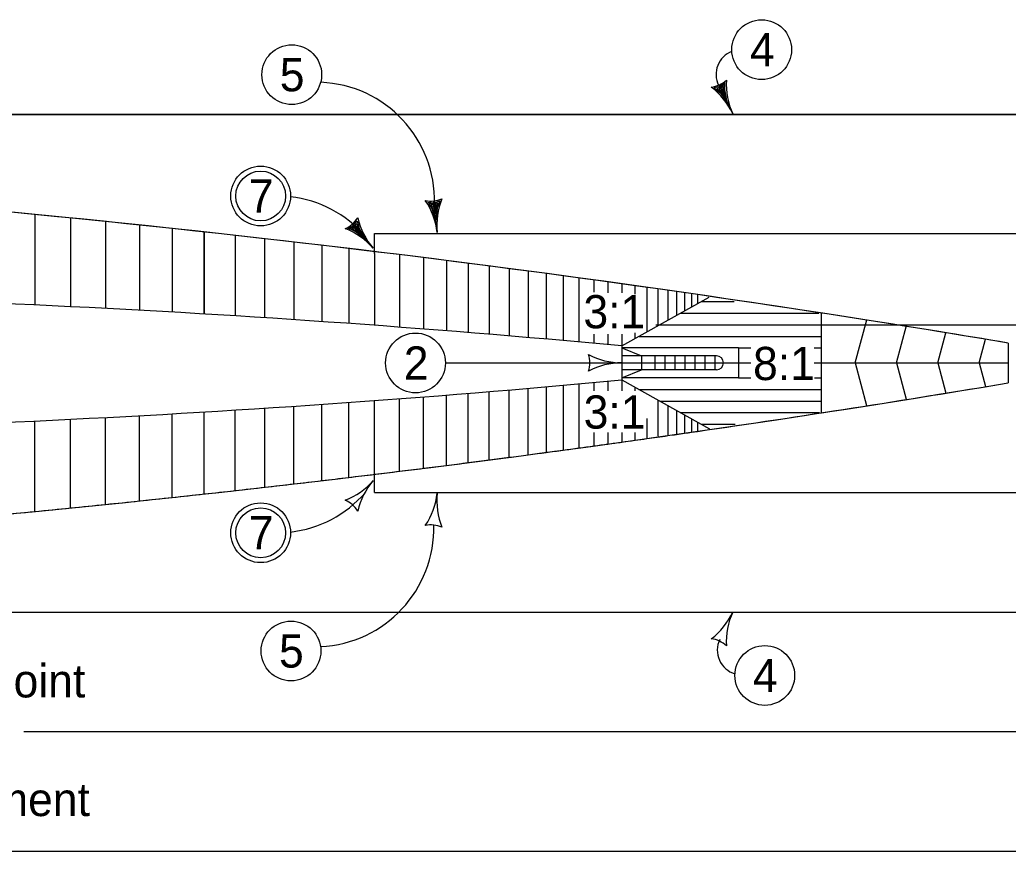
# Model space of a CAD drawing. Extents: x -2135039 to -2131695, y -2139150 to -2136566.
# Drawn here: x -2133841 to -2133246, y -2138502 to -2138002 of the extents above; entities that cross this region are included whole.
import ezdxf

# ---------------------------------------------------------------- set-up
doc = ezdxf.new("R2010")
doc.units = 0
for name, color, linetype in [('dsnStdDimension', 7, 'Continuous'), ('dsnStdLineDrawingWt4', 7, 'Continuous'), ('dsnStdShading', 7, 'Continuous'), ('Level 10', 7, 'Continuous'), ('Level 2', 7, 'Continuous'), ('Level 3', 7, 'Continuous'), ('Level 5', 7, 'Continuous'), ('Level 7', 7, 'Continuous')]:
    doc.layers.add(name, color=color, linetype=linetype)

msp = doc.modelspace()

# ---------------------------------------------------------------- linework, layer by layer
at = {"layer": 'dsnStdDimension'}
for p, q in [((-2133411.43, -2138058.5), (-2133419.43, -2138041.02)), ((-2133589.28, -2138130.01), (-2133591.41, -2138110.91)), ((-2133627.82, -2138139.45), (-2133640.43, -2138124.94)), ((-2133584.37, -2138208.43), (-2133478.24, -2138208.43))]:
    msp.add_line(p, q, dxfattribs=at)
for points in [[(-2133416.03, -2138039.9), (-2133418.98, -2138042.04), (-2133422.57, -2138042.86), (-2133418.9, -2138045.9), (-2133414.67, -2138051.47), (-2133416.16, -2138044.09), (-2133416.19, -2138040.63), (-2133418.71, -2138042.64), (-2133420.94, -2138043.33), (-2133418.53, -2138045.34), (-2133416.08, -2138048.38), (-2133416.69, -2138044.23), (-2133416.91, -2138042.02), (-2133419.54, -2138043.65), (-2133417.31, -2138045.7), (-2133417.59, -2138043.42), (-2133418.56, -2138043.83), (-2133417.83, -2138044.62)], [(-2133594.91, -2138111.69), (-2133591.27, -2138112.01), (-2133587.77, -2138110.87), (-2133589.35, -2138115.37), (-2133590.12, -2138122.32), (-2133592.64, -2138115.22), (-2133594.39, -2138112.24), (-2133591.2, -2138112.67), (-2133588.93, -2138112.11), (-2133589.96, -2138115.07), (-2133590.5, -2138118.94), (-2133592.11, -2138115.07), (-2133593.06, -2138113.06), (-2133589.97, -2138113.11), (-2133590.82, -2138116.02), (-2133591.75, -2138113.91), (-2133590.71, -2138113.77), (-2133590.93, -2138114.82)], [(-2133642.86, -2138127.57), (-2133639.68, -2138125.77), (-2133637.46, -2138122.84), (-2133636.2, -2138127.44), (-2133632.88, -2138133.6), (-2133638.99, -2138129.18), (-2133642.12, -2138127.73), (-2133639.25, -2138126.27), (-2133637.7, -2138124.52), (-2133636.87, -2138127.54), (-2133635.11, -2138131.03), (-2133638.64, -2138128.76), (-2133640.56, -2138127.65), (-2133637.99, -2138125.93), (-2133637.04, -2138128.81), (-2133639, -2138127.61), (-2133638.23, -2138126.89), (-2133637.81, -2138127.88)]]:
    msp.add_lwpolyline(points, dxfattribs=at)
for centre, radius, start, end in [((-2133406.49, -2138034.85), 15, 111.38245, 205.29266), ((-2133662.38, -2138110.89), 71.46, 358.52569, 87.65401), ((-2133426.27, -2138026.09), 16.42, 276.86459, 312.33129), ((-2133450.08, -2138076.19), 42.5, 24.59794, 52.67043), ((-2133372.79, -2138040.81), 42.5, 176.52545, 204.59794), ((-2133685.57, -2138177.98), 70, 40.99055, 83.44185), ((-2133593.23, -2138094.59), 16.42, 258.64458, 294.11128), ((-2133631.51, -2138134.73), 42.5, 6.37793, 34.45042), ((-2133547.04, -2138125.29), 42.5, 158.30544, 186.37793), ((-2133651.19, -2138112.55), 16.42, 293.25942, 328.72612), ((-2133595.74, -2138111.57), 42.5, 192.92028, 220.99277), ((-2133659.9, -2138167.32), 42.5, 40.99277, 69.06526), ((-2133513.87, -2138208.43), 16.42, 342.26665, 17.73335), ((-2133478.24, -2138165.93), 42.5, 241.92751, 270), ((-2133478.24, -2138250.93), 42.5, 90, 118.07249), ((-2133659.9, -2138251.4), 42.5, 290.93474, 319.00723), ((-2133595.74, -2138307.15), 42.5, 139.00723, 167.07972), ((-2133685.57, -2138240.75), 70, 276.55825, 319.00945), ((-2133651.19, -2138306.17), 16.42, 31.27388, 66.74058), ((-2133631.51, -2138282.26), 42.5, 325.54958, 353.62207), ((-2133547.04, -2138291.71), 42.5, 173.62207, 201.69456), ((-2133662.83, -2138307.91), 71.46, 272.66511, 1.47431), ((-2133593.23, -2138322.4), 16.42, 65.88872, 101.35542), ((-2133450.08, -2138340.81), 42.5, 307.32957, 335.40206), ((-2133372.79, -2138376.19), 42.5, 155.40206, 183.47455), ((-2133426.27, -2138390.9), 16.42, 47.66871, 83.13541), ((-2133405.7, -2138381.36), 15, 154.70734, 252.90173)]:
    msp.add_arc(centre, radius, start, end, dxfattribs=at)
at = {"layer": 'dsnStdLineDrawingWt4'}
for p, q in [((-2134688.01, -2138058.83), (-2133150.73, -2138058.83)), ((-2133831.57, -2138119.08), (-2133831.57, -2138173.56)), ((-2133809.97, -2138121.21), (-2133809.97, -2138174.6)), ((-2133788.98, -2138123.33), (-2133788.98, -2138175.67)), ((-2133768.58, -2138125.44), (-2133768.58, -2138176.76)), ((-2133748.78, -2138127.54), (-2133748.78, -2138177.87)), ((-2133729.58, -2138129.61), (-2133729.58, -2138179)), ((-2133729.58, -2138179), (-2133729.58, -2138129.61)), ((-2133710.98, -2138131.67), (-2133710.98, -2138180.14)), ((-2133626.99, -2138142.5), (-2133626.99, -2138130.5)), ((-2133626.99, -2138130.5), (-2132916.93, -2138130.5)), ((-2133693.19, -2138133.67), (-2133693.19, -2138181.27)), ((-2133675.58, -2138135.69), (-2133675.58, -2138182.43)), ((-2133658.78, -2138137.65), (-2133658.78, -2138183.58)), ((-2133642.58, -2138139.57), (-2133642.58, -2138184.72)), ((-2133626.98, -2138142.5), (-2133626.98, -2138185.85)), ((-2133611.98, -2138143.29), (-2133611.98, -2138186.97)), ((-2133597.58, -2138145.08), (-2133597.58, -2138188.07)), ((-2133583.78, -2138146.82), (-2133583.78, -2138189.15)), ((-2133570.58, -2138148.5), (-2133570.58, -2138190.21)), ((-2133557.98, -2138150.12), (-2133557.98, -2138191.24)), ((-2133545.98, -2138151.69), (-2133545.98, -2138192.24)), ((-2133534.58, -2138153.19), (-2133534.58, -2138193.21)), ((-2133523.78, -2138154.63), (-2133523.78, -2138194.14)), ((-2133513.58, -2138156), (-2133513.58, -2138195.04)), ((-2133503.98, -2138157.3), (-2133503.98, -2138195.89)), ((-2133494.98, -2138158.53), (-2133494.98, -2138165.9)), ((-2133486.58, -2138159.69), (-2133486.58, -2138166.25)), ((-2133478.18, -2138160.85), (-2133478.18, -2138166.25)), ((-2133470.38, -2138161.94), (-2133470.38, -2138167.05)), ((-2133463.18, -2138162.96), (-2133463.18, -2138189.9)), ((-2133456.58, -2138163.89), (-2133456.58, -2138186.2)), ((-2133450.58, -2138164.74), (-2133450.58, -2138182.85)), ((-2133445.18, -2138165.52), (-2133445.18, -2138179.83)), ((-2133440.38, -2138166.2), (-2133440.38, -2138177.14)), ((-2133436.18, -2138166.81), (-2133436.18, -2138174.79)), ((-2133432.58, -2138167.33), (-2133432.58, -2138172.78)), ((-2133478.13, -2138198.26), (-2133425.54, -2138168.84)), ((-2133430.24, -2138171.55), (-2133410.47, -2138171.55)), ((-2133442.86, -2138178.53), (-2133359.66, -2138178.53)), ((-2133358.24, -2138178.73), (-2133358.24, -2138238.26)), ((-2133455.33, -2138185.51), (-2133358.24, -2138185.51)), ((-2133337.7, -2138208.46), (-2133330.77, -2138182.6)), ((-2133494.98, -2138191.1), (-2133494.98, -2138196.71)), ((-2133486.58, -2138191.25), (-2133486.58, -2138197.48)), ((-2133478.18, -2138191.25), (-2133478.18, -2138225.31)), ((-2133470.38, -2138190.45), (-2133470.38, -2138193.92)), ((-2133312.84, -2138208.5), (-2133306.82, -2138186.03)), ((-2133287.99, -2138208.5), (-2133283.15, -2138190.4)), ((-2133486.58, -2138192), (-2133486.58, -2138193.21)), ((-2133467.81, -2138192.49), (-2133358.24, -2138192.49)), ((-2133263.15, -2138208.5), (-2133259.33, -2138194.25)), ((-2133245.58, -2138196.5), (-2133245.58, -2138220.5)), ((-2133478.24, -2138198.26), (-2133478.24, -2138218.73)), ((-2133408.04, -2138199.46), (-2133478.24, -2138199.46)), ((-2133478.24, -2138199.46), (-2133466.24, -2138204.26)), ((-2133408.04, -2138199.46), (-2133408.04, -2138217.46)), ((-2133408.04, -2138199.46), (-2133400.53, -2138199.46)), ((-2133362.36, -2138199.46), (-2133358.24, -2138199.46)), ((-2133466.24, -2138204.26), (-2133478.24, -2138204.26)), ((-2133478.24, -2138208.5), (-2133400.53, -2138208.5)), ((-2133421.24, -2138204.26), (-2133466.24, -2138204.26)), ((-2133466.24, -2138204.26), (-2133466.24, -2138212.66)), ((-2133458.24, -2138204.26), (-2133458.24, -2138212.66)), ((-2133452.24, -2138204.26), (-2133452.24, -2138212.66)), ((-2133446.24, -2138204.26), (-2133446.24, -2138212.66)), ((-2133440.24, -2138204.26), (-2133440.24, -2138212.66)), ((-2133434.24, -2138204.26), (-2133434.24, -2138212.66)), ((-2133428.24, -2138204.26), (-2133428.24, -2138212.66)), ((-2133422.24, -2138204.26), (-2133422.24, -2138212.66)), ((-2133362.36, -2138208.5), (-2133245.58, -2138208.5)), ((-2133337.7, -2138208.46), (-2133330.83, -2138234.08)), ((-2133312.84, -2138208.5), (-2133306.98, -2138230.37)), ((-2133288, -2138208.5), (-2133283.15, -2138226.59)), ((-2133263.15, -2138208.5), (-2133259.33, -2138222.75)), ((-2133478.24, -2138217.46), (-2133466.24, -2138212.66)), ((-2133466.24, -2138212.66), (-2133478.24, -2138212.66)), ((-2133421.24, -2138212.66), (-2133466.24, -2138212.66)), ((-2133503.98, -2138221.1), (-2133503.98, -2138259.7)), ((-2133494.98, -2138220.29), (-2133494.98, -2138225.31)), ((-2133486.58, -2138219.52), (-2133486.58, -2138225.31)), ((-2133408.04, -2138217.46), (-2133478.24, -2138217.46)), ((-2133478.12, -2138218.73), (-2133425.45, -2138248.14)), ((-2133408.04, -2138217.46), (-2133400.53, -2138217.46)), ((-2133362.2, -2138217.46), (-2133358.24, -2138217.46)), ((-2133570.58, -2138268.5), (-2133570.58, -2138226.79)), ((-2133557.98, -2138266.88), (-2133557.98, -2138225.76)), ((-2133545.98, -2138265.31), (-2133545.98, -2138224.75)), ((-2133534.58, -2138263.81), (-2133534.58, -2138223.79)), ((-2133523.78, -2138222.85), (-2133523.78, -2138262.37)), ((-2133513.58, -2138221.96), (-2133513.58, -2138261)), ((-2133470.38, -2138223.06), (-2133470.38, -2138225.31)), ((-2133467.89, -2138224.44), (-2133358.24, -2138224.44)), ((-2133642.58, -2138277.42), (-2133642.58, -2138232.28)), ((-2133626.98, -2138275.54), (-2133626.98, -2138231.14)), ((-2133611.98, -2138273.71), (-2133611.98, -2138230.03)), ((-2133597.58, -2138271.92), (-2133597.58, -2138228.93)), ((-2133583.78, -2138270.18), (-2133583.78, -2138227.84)), ((-2133456.58, -2138230.76), (-2133456.58, -2138252.52)), ((-2133455.4, -2138231.42), (-2133358.24, -2138231.42)), ((-2133748.78, -2138289.46), (-2133748.78, -2138239.12)), ((-2133729.58, -2138287.39), (-2133729.58, -2138237.99)), ((-2133710.98, -2138285.33), (-2133710.98, -2138236.86)), ((-2133692.98, -2138283.3), (-2133692.98, -2138235.71)), ((-2133675.58, -2138281.31), (-2133675.58, -2138234.56)), ((-2133658.78, -2138279.35), (-2133658.78, -2138233.42)), ((-2133450.58, -2138234.11), (-2133450.58, -2138252.25)), ((-2133445.18, -2138237.12), (-2133445.18, -2138251.48)), ((-2133442.9, -2138238.4), (-2133359.2, -2138238.4)), ((-2133831.57, -2138297.92), (-2133831.57, -2138243.43)), ((-2133809.97, -2138295.79), (-2133809.97, -2138242.39)), ((-2133788.98, -2138293.67), (-2133788.98, -2138241.33)), ((-2133768.58, -2138291.56), (-2133768.58, -2138240.23)), ((-2133463.18, -2138242.01), (-2133463.18, -2138254.04)), ((-2133440.38, -2138239.8), (-2133440.38, -2138250.79)), ((-2133436.18, -2138242.15), (-2133436.18, -2138250.19)), ((-2133432.58, -2138244.16), (-2133432.58, -2138249.67)), ((-2133494.98, -2138250.31), (-2133494.98, -2138258.47)), ((-2133486.58, -2138250.29), (-2133486.58, -2138257.31)), ((-2133478.18, -2138250.31), (-2133478.18, -2138256.14)), ((-2133470.38, -2138250.31), (-2133470.38, -2138255.05)), ((-2133430.24, -2138245.37), (-2133409.99, -2138245.37)), ((-2133626.99, -2138286.5), (-2133626.99, -2138274.5)), ((-2133626.99, -2138286.5), (-2132913.93, -2138286.5)), ((-2134688.98, -2138358.5), (-2133150.73, -2138358.5)), ((-2134750.5, -2138502.5), (-2132911.43, -2138502.5))]:
    msp.add_line(p, q, dxfattribs=at)
for centre, radius, start, end in [((-2134663.92, -2146675.65), 8596.96, 80.503855, 86.524933), ((-2134186.74, -2145798.55), 7633.25, 84.674283, 90), ((-2134186.74, -2130618.44), 7633.25, 270, 275.326608), ((-2134663.85, -2129742.69), 8595.62, 273.476084, 279.497162)]:
    msp.add_arc(centre, radius, start, end, dxfattribs=at)
at = {"layer": 'dsnStdShading'}
for p, q in [((-2133150.73, -2138058.83), (-2134688.01, -2138058.83)), ((-2133693.19, -2138133.67), (-2133693.19, -2138133.67)), ((-2133330.79, -2138182.68), (-2133330.77, -2138182.6)), ((-2133245.58, -2138196.5), (-2133245.58, -2138208.5)), ((-2133245.58, -2138208.5), (-2133245.58, -2138220.5)), ((-2133440.38, -2138250.79), (-2133440.38, -2138250.79)), ((-2133436.18, -2138250.19), (-2133436.18, -2138250.19)), ((-2133432.58, -2138249.67), (-2133432.58, -2138249.67)), ((-2133478.18, -2138256.14), (-2133478.18, -2138256.14)), ((-2133470.38, -2138255.05), (-2133470.38, -2138255.05)), ((-2133463.18, -2138254.04), (-2133463.18, -2138254.04)), ((-2133450.58, -2138252.25), (-2133450.58, -2138252.25)), ((-2133445.18, -2138251.48), (-2133445.18, -2138251.48)), ((-2133523.78, -2138262.37), (-2133523.78, -2138262.37)), ((-2133513.58, -2138261), (-2133513.58, -2138261)), ((-2133503.98, -2138259.7), (-2133503.98, -2138259.7)), ((-2133494.98, -2138258.47), (-2133494.98, -2138258.47)), ((-2133486.58, -2138257.31), (-2133486.58, -2138257.31)), ((-2133570.58, -2138268.5), (-2133570.58, -2138268.5)), ((-2133557.98, -2138266.88), (-2133557.98, -2138266.88)), ((-2133545.98, -2138265.31), (-2133545.98, -2138265.31)), ((-2133534.58, -2138263.81), (-2133534.58, -2138263.81)), ((-2133611.98, -2138273.71), (-2133611.98, -2138273.71)), ((-2133597.58, -2138271.92), (-2133597.58, -2138271.92)), ((-2133583.78, -2138270.18), (-2133583.78, -2138270.18)), ((-2133658.78, -2138279.35), (-2133658.78, -2138279.35)), ((-2133642.58, -2138277.42), (-2133642.58, -2138277.42)), ((-2133626.98, -2138275.54), (-2133626.98, -2138275.54)), ((-2133710.98, -2138285.33), (-2133710.98, -2138285.33)), ((-2133692.98, -2138283.3), (-2133692.98, -2138283.3)), ((-2133675.58, -2138281.31), (-2133675.58, -2138281.31)), ((-2133768.58, -2138291.56), (-2133768.58, -2138291.56)), ((-2133748.78, -2138289.46), (-2133748.78, -2138289.46)), ((-2133729.58, -2138287.39), (-2133729.58, -2138287.39)), ((-2133831.57, -2138297.92), (-2133831.57, -2138297.92)), ((-2133809.97, -2138295.79), (-2133809.97, -2138295.79)), ((-2133788.98, -2138293.67), (-2133788.98, -2138293.67)), ((-2134688.98, -2138358.5), (-2133150.73, -2138358.5))]:
    msp.add_line(p, q, dxfattribs=at)
for points in [[(-2133693.19, -2138133.67), (-2133693.19, -2138133.67)], [(-2133330.77, -2138182.6), (-2133330.78, -2138182.68)], [(-2133440.38, -2138250.79), (-2133440.38, -2138250.79)], [(-2133436.18, -2138250.19), (-2133436.18, -2138250.19)], [(-2133432.58, -2138249.67), (-2133432.58, -2138249.67)], [(-2133478.18, -2138256.14), (-2133478.18, -2138256.14)], [(-2133470.38, -2138255.05), (-2133470.38, -2138255.05)], [(-2133463.18, -2138254.04), (-2133463.18, -2138254.04)], [(-2133450.58, -2138252.25), (-2133450.58, -2138252.25)], [(-2133445.18, -2138251.48), (-2133445.18, -2138251.48)], [(-2133523.78, -2138262.37), (-2133523.78, -2138262.37)], [(-2133513.58, -2138261), (-2133513.58, -2138261)], [(-2133503.98, -2138259.7), (-2133503.98, -2138259.7)], [(-2133494.98, -2138258.47), (-2133494.98, -2138258.47)], [(-2133486.58, -2138257.31), (-2133486.58, -2138257.31)], [(-2133570.58, -2138268.5), (-2133570.58, -2138268.5)], [(-2133557.98, -2138266.88), (-2133557.98, -2138266.88)], [(-2133545.98, -2138265.31), (-2133545.98, -2138265.31)], [(-2133534.58, -2138263.81), (-2133534.58, -2138263.81)], [(-2133611.98, -2138273.71), (-2133611.98, -2138273.71)], [(-2133597.58, -2138271.92), (-2133597.58, -2138271.92)], [(-2133583.78, -2138270.18), (-2133583.78, -2138270.18)], [(-2133658.78, -2138279.35), (-2133658.78, -2138279.35)], [(-2133642.58, -2138277.42), (-2133642.58, -2138277.42)], [(-2133626.98, -2138275.54), (-2133626.98, -2138275.54)], [(-2133710.98, -2138285.33), (-2133710.98, -2138285.33)], [(-2133692.98, -2138283.3), (-2133692.98, -2138283.3)], [(-2133675.58, -2138281.31), (-2133675.58, -2138281.31)], [(-2133768.58, -2138291.56), (-2133768.58, -2138291.56)], [(-2133748.78, -2138289.46), (-2133748.78, -2138289.46)], [(-2133729.58, -2138287.39), (-2133729.58, -2138287.39)], [(-2133831.57, -2138297.92), (-2133831.57, -2138297.92)], [(-2133809.97, -2138295.79), (-2133809.97, -2138295.79)], [(-2133788.98, -2138293.67), (-2133788.98, -2138293.67)]]:
    msp.add_lwpolyline(points, dxfattribs=at)
for centre, radius, start, end in [((-2134663.92, -2146675.65), 8596.96, 83.516635, 86.489906), ((-2134663.92, -2146675.65), 8596.96, 81.079166, 83.516635), ((-2134663.92, -2146675.65), 8596.96, 80.503855, 81.079108), ((-2134663.85, -2129742.69), 8595.62, 278.235608, 279.497162), ((-2134663.85, -2129742.69), 8595.62, 278.150755, 278.183078), ((-2134663.85, -2129742.69), 8595.62, 278.183078, 278.211362), ((-2134663.85, -2129742.69), 8595.62, 278.211363, 278.235608), ((-2134663.85, -2129742.69), 8595.62, 277.872075, 277.928603), ((-2134663.85, -2129742.69), 8595.62, 277.928604, 277.981101), ((-2134663.85, -2129742.69), 8595.62, 277.981101, 278.029566), ((-2134663.85, -2129742.69), 8595.62, 278.029566, 278.114394), ((-2134663.85, -2129742.69), 8595.62, 278.114394, 278.150754), ((-2134663.85, -2129742.69), 8595.62, 277.549203, 277.621827), ((-2134663.85, -2129742.69), 8595.62, 277.621828, 277.690429), ((-2134663.85, -2129742.69), 8595.62, 277.690429, 277.755005), ((-2134663.85, -2129742.69), 8595.62, 277.755006, 277.815555), ((-2134663.85, -2129742.69), 8595.62, 277.815555, 277.872075), ((-2134663.85, -2129742.69), 8595.62, 277.218509, 277.307207), ((-2134663.85, -2129742.69), 8595.62, 277.307207, 277.39189), ((-2134663.85, -2129742.69), 8595.62, 277.39189, 277.472556), ((-2134663.85, -2129742.69), 8595.62, 277.472557, 277.549202), ((-2134663.85, -2129742.69), 8595.62, 276.928343, 277.029074), ((-2134663.85, -2129742.69), 8595.62, 277.029074, 277.125797), ((-2134663.85, -2129742.69), 8595.62, 277.125797, 277.218508), ((-2134663.85, -2129742.69), 8595.62, 276.602118, 276.714862), ((-2134663.85, -2129742.69), 8595.62, 276.714862, 276.823604), ((-2134663.85, -2129742.69), 8595.62, 276.823604, 276.928342), ((-2134663.85, -2129742.69), 8595.62, 276.239899, 276.364634), ((-2134663.85, -2129742.69), 8595.62, 276.364634, 276.485375), ((-2134663.85, -2129742.69), 8595.62, 276.485375, 276.602118), ((-2134663.85, -2129742.69), 8595.62, 275.841746, 275.978452), ((-2134663.85, -2129742.69), 8595.62, 275.978452, 276.11117), ((-2134663.85, -2129742.69), 8595.62, 276.111171, 276.239898), ((-2134663.85, -2129742.69), 8595.62, 275.407719, 275.556376), ((-2134663.85, -2129742.69), 8595.62, 275.556377, 275.701053), ((-2134663.85, -2129742.69), 8595.62, 275.701053, 275.841745)]:
    msp.add_arc(centre, radius, start, end, dxfattribs=at)
at = {"layer": 'Level 10'}
for centre in [(-2133393.99, -2138019.85), (-2133676.87, -2138034.92), (-2133695.57, -2138107.97), (-2133602.37, -2138208.49), (-2133695.57, -2138310.74), (-2133677.31, -2138381.91), (-2133392.14, -2138396.65)]:
    msp.add_circle(centre, 18, dxfattribs=at)
at = {"layer": 'Level 2'}
msp.add_line((-2133457.76, -2138185.58), (-2133066.86, -2138185.58), dxfattribs=at)
for centre in [(-2133695.57, -2138107.97), (-2133695.57, -2138310.74)]:
    msp.add_circle(centre, 15, dxfattribs=at)
at = {"layer": 'Level 3'}
msp.add_line((-2133838.08, -2138430.5), (-2132911.43, -2138430.5), dxfattribs=at)
at = {"layer": 'Level 5'}
msp.add_arc((-2133421.24, -2138208.46), 4.2, 270, 90, dxfattribs=at)

# ---------------------------------------------------------------- texts
at = {"layer": 'Level 7'}
for s, p in [('4', (-2133401.08, -2138029.85)), ('5', (-2133684.08, -2138044.92)), ('7', (-2133702.71, -2138117.97)), ('3:1', (-2133501.28, -2138187.63)), ('2', (-2133609.4, -2138218.49)), ('8:1', (-2133399.17, -2138218.81)), ('3:1', (-2133501.13, -2138248.01)), ('7', (-2133702.71, -2138320.74)), ('5', (-2133684.52, -2138391.91)), ('4', (-2133399.23, -2138406.65)), ("'L-2'  or 'KT-2' Joint", (-2134028.22, -2138409.89)), ('Existing Pavement', (-2134019.9, -2138481.33))]:
    msp.add_text(s, height=20, dxfattribs=at).set_placement(p)

doc.saveas('drawing.dxf')
